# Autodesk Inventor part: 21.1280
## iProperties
Created: 2006-02
Part Number: 21.1280
Material: Steel, Mild
Description: M8X22 SHCS
Document SubType Name: Modeling
Standard: DIN 7984
Designer: Andy Moles
Standards Organization: DIN
Language: en-US
Size Designation: M8 x 20
Categories: <MemberInstance><Categories><Category DisplayName="Fasteners" InternalName="e4da775c-781d-43d5-af7c-5136215cf5a6" Mnemonic="FSTN"><Category DisplayName="Bolts"
Density: 7.86 g/cm^3
Mass: 13.0532 g
Surface Area: 10.6794 cm^2
Volume: 1.66071 cm^3
Vendor: S
Author: Andy Moles
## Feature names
1. Body [Revolution]
2. Slot [Extrusion]
3. Fillet1
4. Chamfer1
